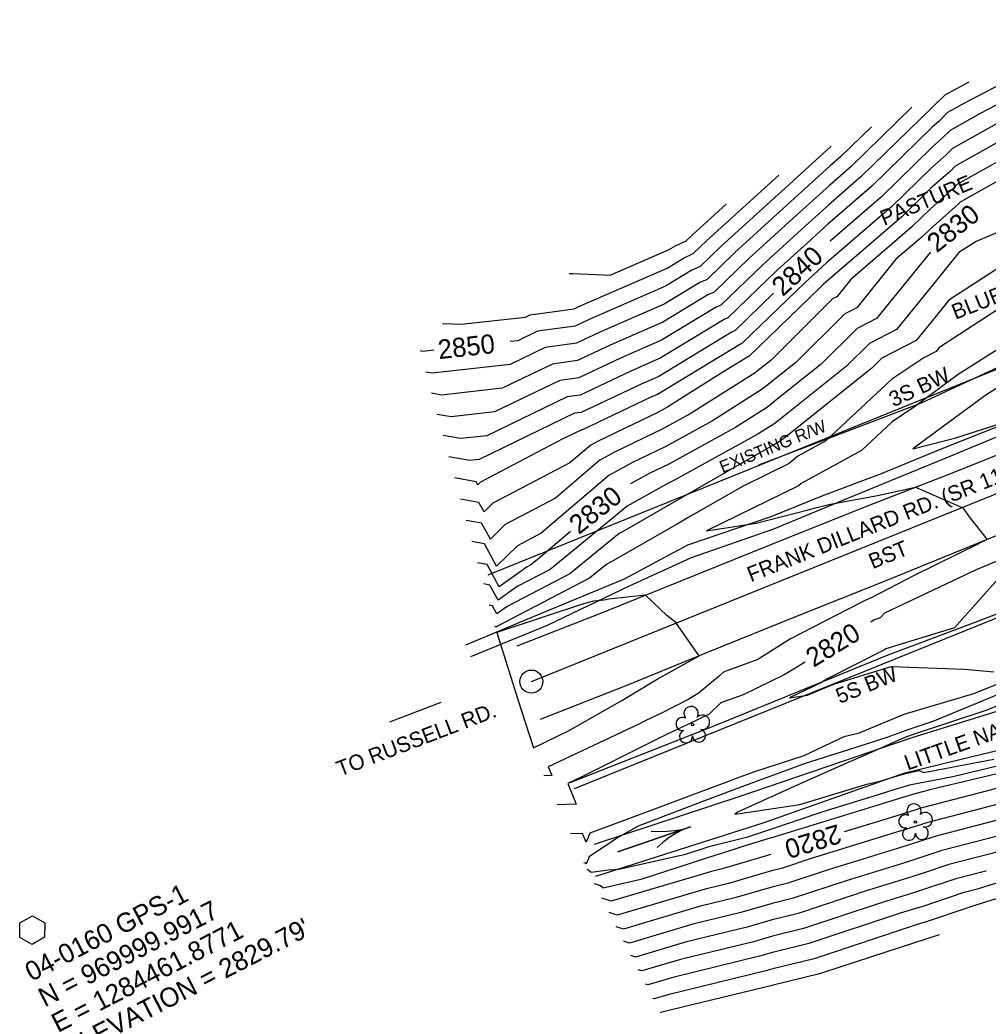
# Model space of a CAD drawing. Extents: x 1284446 to 1285480, y 969739 to 970628.
# Drawn here: x 1284458.6 to 1284710.8, y 969978.1 to 970236.9 of the extents above; entities that cross this region are included whole.
import ezdxf

# ---------------------------------------------------------------- set-up
doc = ezdxf.new("R2010")
doc.units = 0
for name, color, linetype in [('CTL Primary Horizontal and Vertical CELL', 7, 'Continuous'), ('CTL Primary Horizontal and Vertical Text', 7, 'Continuous'), ('Default', 7, 'Continuous'), ('Exist Horizontal Alignment', 7, 'Continuous'), ('Exist Horizontal Alignment Point', 7, 'Continuous'), ('Exist Hydro Jurisdictional Stream or Body of Water', 7, 'Continuous'), ('Exist Hydro Jurisdictional Stream or Body of Water Text', 7, 'Continuous'), ('Exist Hydro River Flow Arrow CELL', 7, 'Continuous'), ('Exist Other Culture Fence Line', 7, 'Continuous'), ('Exist Other Culture Fence Line Text', 7, 'Continuous'), ('Exist Right of Way Line', 7, 'Continuous'), ('Exist Right of Way Line Text', 7, 'Continuous'), ('Exist Roads EOP', 7, 'Continuous'), ('Exist Roads EOP Leader', 7, 'Continuous'), ('Exist Roads EOP Text', 7, 'Continuous'), ('Exist Utilities Power Joint Use Telephone Text', 7, 'Continuous'), ('Exist Utilities Telephone UG Cable SUE LOS D', 7, 'Continuous'), ('Exist Vegetation Tree CELL', 7, 'Continuous'), ('Exist Vegetation Woods Line Text', 7, 'Continuous')]:
    doc.layers.add(name, color=color, linetype=linetype)

msp = doc.modelspace()

# ---------------------------------------------------------------- linework, layer by layer
at = {"layer": 'CTL Primary Horizontal and Vertical CELL'}
msp.add_line((1284461.88, 969999.99), (1284461.88, 969999.99), dxfattribs=at)
msp.add_lwpolyline([(1284458.65, 970001.86), (1284461.9, 970003.68), (1284465.15, 970001.89), (1284465.1, 969998.16), (1284461.85, 969996.28), (1284458.65, 969998.09)], close=True, dxfattribs=at)
at = {"layer": 'Default'}
for points in [[(1284750.39, 970236.94), (1284749.29, 970236), (1284745.73, 970232.97), (1284744.91, 970232.37), (1284733.62, 970226.77), (1284728.14, 970222.74), (1284727.72, 970222.5), (1284708.72, 970212.53), (1284700.87, 970208.14), (1284698.91, 970206.2), (1284696.12, 970203.72), (1284683.01, 970190.92), (1284669.6, 970179.36)], [(1284739.84, 970233.74), (1284729.08, 970228.4), (1284727.62, 970227.33), (1284727.51, 970227.26), (1284704.48, 970215.18), (1284700.22, 970212.79), (1284697.9, 970210.5), (1284696.24, 970209.02), (1284680.37, 970193.53), (1284669.07, 970183.79), (1284663.63, 970178.84), (1284655.84, 970171.76), (1284643.02, 970159.37), (1284642.05, 970158.93), (1284625.37, 970148.84), (1284617.73, 970145.52), (1284604.5, 970139.27), (1284601.13, 970138.8), (1284580.23, 970128.69), (1284573.36, 970127.93), (1284568.84, 970128.73)], [(1284705.76, 970220.72), (1284700.24, 970217.82), (1284699.57, 970217.45), (1284696.89, 970214.81), (1284696.36, 970214.33), (1284677.73, 970196.14), (1284669.25, 970188.83), (1284662.22, 970182.44), (1284652.17, 970173.3), (1284641.21, 970162.72), (1284639.93, 970162.13), (1284625.73, 970153.54), (1284615.03, 970148.89), (1284604.19, 970143.76), (1284599.21, 970143.08), (1284582.24, 970134.87), (1284570.92, 970133.61), (1284567.34, 970134.25)], [(1284690.89, 970214.19), (1284675.09, 970198.76), (1284669.43, 970193.87), (1284660.82, 970186.05), (1284648.5, 970174.85), (1284639.41, 970166.06), (1284637.82, 970165.34), (1284626.09, 970158.24), (1284612.33, 970152.25), (1284603.88, 970148.26), (1284597.3, 970147.36), (1284584.26, 970141.05), (1284568.47, 970139.29), (1284565.84, 970139.76)], [(1284680.4, 970209.13), (1284672.45, 970201.37), (1284669.6, 970198.91), (1284659.41, 970189.65), (1284644.83, 970176.39), (1284637.6, 970169.4), (1284635.7, 970168.54), (1284626.45, 970162.94), (1284609.63, 970155.62), (1284603.56, 970152.76), (1284595.39, 970151.64), (1284586.27, 970147.23), (1284566.02, 970144.98), (1284564.34, 970145.28)], [(1284712.97, 970209.89), (1284701.53, 970203.48), (1284699.92, 970201.9), (1284696, 970198.41), (1284685.65, 970188.31), (1284668.72, 970173.71), (1284666.44, 970171.64), (1284663.18, 970168.68), (1284646.64, 970152.69), (1284646.28, 970152.52), (1284624.65, 970139.44), (1284623.14, 970138.79), (1284605.12, 970130.27), (1284604.96, 970130.25), (1284600, 970127.85), (1284578.6, 970116.64), (1284577.88, 970115.92), (1284577.45, 970116.7), (1284571.84, 970117.7)], [(1284717.21, 970207.24), (1284702.18, 970198.82), (1284700.93, 970197.59), (1284695.88, 970193.1), (1284688.29, 970185.69), (1284668.54, 970168.67), (1284667.85, 970168.04), (1284666.86, 970167.14), (1284648.45, 970149.34), (1284648.39, 970149.32), (1284642.34, 970145.66), (1284627.41, 970136.21), (1284624.95, 970134.85), (1284609.19, 970127.31), (1284607.28, 970126.25), (1284601.82, 970121.6), (1284581.81, 970111.11), (1284579.52, 970108.85), (1284578.16, 970111.33), (1284573.34, 970112.18)], [(1284721.46, 970204.6), (1284702.83, 970194.17), (1284701.94, 970193.29), (1284695.76, 970187.79), (1284690.93, 970183.08), (1284675.05, 970169.4), (1284671.37, 970164.87), (1284670.27, 970164.29), (1284654.16, 970148.31), (1284650.71, 970145.57), (1284650.1, 970145.08), (1284633.22, 970134.4), (1284625.91, 970130.37), (1284613.68, 970124.52), (1284609.66, 970122.29), (1284598.1, 970112.45), (1284585.02, 970105.59), (1284581.15, 970101.78), (1284578.88, 970105.95), (1284574.84, 970106.67)], [(1284669.9, 970204.07), (1284669.81, 970203.98), (1284669.78, 970203.95), (1284658.01, 970193.25), (1284641.15, 970177.93), (1284635.79, 970172.75), (1284633.59, 970171.75), (1284626.8, 970167.64), (1284606.92, 970158.99), (1284603.25, 970157.25), (1284593.47, 970155.91), (1284588.29, 970153.4), (1284586.34, 970153.19)], [(1284725.7, 970201.95), (1284703.48, 970189.51), (1284702.94, 970188.98), (1284695.64, 970182.48), (1284693.57, 970180.47), (1284686.78, 970174.62), (1284676.54, 970162.02), (1284673.48, 970160.44), (1284660.74, 970147.79), (1284653.07, 970141.7), (1284651.71, 970140.62), (1284639.03, 970132.59), (1284626.87, 970125.89), (1284618.18, 970121.74), (1284612.03, 970118.32), (1284594.38, 970103.3), (1284588.23, 970100.07), (1284582.79, 970094.71), (1284579.59, 970100.58), (1284576.34, 970101.15)], [(1284568.82, 970157.94), (1284569, 970157.93), (1284573.54, 970157.72), (1284590.3, 970159.58), (1284591.56, 970160.19), (1284602.94, 970161.75), (1284604.22, 970162.35), (1284627.16, 970172.34), (1284631.48, 970174.95), (1284633.98, 970176.09), (1284637.48, 970179.47), (1284656.27, 970196.55)], [(1284601.71, 970170.95), (1284602.73, 970170.9), (1284608.57, 970170.63), (1284612.39, 970170.45), (1284627.52, 970177.04), (1284629.36, 970178.16), (1284632.18, 970179.43), (1284633.81, 970181.01), (1284642.59, 970189)], [(1284727.79, 970187.79), (1284707.63, 970179.29), (1284703.18, 970176.39), (1284696.36, 970167.99), (1284686.89, 970156.34), (1284679.91, 970152.72), (1284673.91, 970146.76), (1284657.79, 970133.96), (1284654.94, 970131.69), (1284650.64, 970128.97), (1284628.78, 970116.93), (1284627.18, 970116.17), (1284616.78, 970110.39), (1284613.23, 970107.37), (1284596.77, 970093.9), (1284588.14, 970089.41), (1284583.18, 970085.86), (1284581.01, 970089.82), (1284579.33, 970090.12)], [(1284695.8, 970176.51), (1284695.71, 970176.39), (1284681.71, 970159.18), (1284676.7, 970156.58), (1284667.33, 970147.28), (1284655.43, 970137.83), (1284653.32, 970136.15), (1284644.84, 970130.78), (1284627.82, 970121.41), (1284622.68, 970118.95), (1284617.64, 970116.15)], [(1284714.06, 970172.78), (1284700.58, 970163.97), (1284697.01, 970159.58), (1284692.06, 970153.49), (1284683.13, 970148.86), (1284680.49, 970146.24), (1284660.15, 970130.09), (1284656.55, 970127.22), (1284656.45, 970127.16), (1284655.44, 970126.6), (1284630.92, 970112.52), (1284622.94, 970107.94), (1284615.56, 970103.71), (1284614.69, 970103.23), (1284601.88, 970092.75), (1284585.51, 970084.23), (1284582.87, 970082.34), (1284581.72, 970084.45), (1284580.83, 970084.61)], [(1284748.03, 970170.64), (1284743.49, 970166.53), (1284743.11, 970160.61), (1284730.72, 970152.47), (1284717.68, 970144.01), (1284710.17, 970139.24), (1284709.56, 970138.79), (1284691.19, 970125.24), (1284702.36, 970128.13), (1284714.55, 970132.09), (1284714.9, 970132.2), (1284715.19, 970132.29), (1284715.26, 970132.31)], [(1284654.92, 970165.78), (1284644.83, 970156.03), (1284644.16, 970155.73), (1284625.01, 970144.14), (1284620.44, 970142.15), (1284604.81, 970134.77), (1284603.04, 970134.53), (1284578.21, 970122.51), (1284575.81, 970122.24), (1284570.34, 970123.22)], [(1284720.49, 970166.27), (1284697.97, 970151.55), (1284697.66, 970151.17), (1284697.23, 970150.65), (1284694.07, 970149.01), (1284685.66, 970143.42), (1284668.55, 970127.4), (1284661.22, 970123.37), (1284658.97, 970121.46), (1284646.96, 970115.58), (1284634.03, 970108.16), (1284630.05, 970105.87), (1284613.42, 970096.34), (1284611.46, 970095.25), (1284607, 970091.6), (1284582.87, 970079.05), (1284582.57, 970078.83), (1284582.44, 970079.07), (1284582.33, 970079.09)], [(1284724.54, 970158.35), (1284703.64, 970145.09), (1284703.35, 970144.87), (1284691.64, 970136.24), (1284685.75, 970132.32), (1284677.8, 970124.88), (1284662.11, 970116.25), (1284661.41, 970115.66), (1284637.41, 970103.92), (1284650.4, 970105.95), (1284663.92, 970109.43), (1284665.84, 970109.91), (1284669.26, 970110.82), (1284681.92, 970113.1), (1284691.88, 970115.32), (1284703.36, 970110.26), (1284704.18, 970109.92), (1284706.11, 970107.2), (1284710.54, 970101.68), (1284708.52, 970100.7), (1284708.24, 970100.56), (1284691.48, 970092.28), (1284680.5, 970086.62), (1284678.5, 970085.7), (1284677.5, 970085.19), (1284677.37, 970085.11), (1284659.3, 970075.84), (1284650.8, 970070.44), (1284642.99, 970067.59), (1284641.83, 970067.18), (1284640.7, 970066.09), (1284635.28, 970061.56), (1284632.69, 970060.04), (1284625.76, 970056.44), (1284621.62, 970054.54), (1284619.65, 970053.55), (1284596.25, 970042.5), (1284597.15, 970040.23), (1284595.1, 970040.17)], [(1284566.46, 970150.98), (1284563.58, 970150.66), (1284562.84, 970150.79)], [(1284770.67, 970122.38), (1284755.04, 970114.8), (1284747.18, 970111.12), (1284744.66, 970109.99), (1284744.6, 970109.97), (1284719.18, 970098.66), (1284717.11, 970097.76), (1284716.01, 970097.26), (1284707.63, 970093.8), (1284683.78, 970082.51), (1284682.67, 970081.27), (1284681.13, 970080.8), (1284680.2, 970080.2)], [(1284602, 970103.79), (1284593.33, 970096.41), (1284591.66, 970095.05), (1284590.78, 970094.59), (1284583.48, 970089.37), (1284580.3, 970095.2), (1284577.83, 970095.64)], [(1284714.86, 970093.11), (1284708.34, 970085.8), (1284701.98, 970078.68), (1284684.11, 970073.22), (1284683.76, 970072.99), (1284669.03, 970065.5), (1284667.39, 970064.48), (1284659.08, 970060.44), (1284663.71, 970061.19), (1284668.67, 970063.23), (1284670.33, 970063.91), (1284685.5, 970068.61), (1284704.66, 970067.91), (1284712.27, 970067.27)], [(1284601.54, 970051.84), (1284615.42, 970059.75), (1284617.13, 970060.83), (1284619.13, 970062.01), (1284624.57, 970065.33), (1284635.49, 970071.4), (1284634.85, 970072.38), (1284629.43, 970080.04), (1284627.09, 970081.94), (1284621.51, 970087.19), (1284611.99, 970086.11), (1284610.76, 970085.89), (1284608.02, 970085.59), (1284605.37, 970084.91), (1284582.86, 970077.5), (1284588.28, 970060), (1284592.38, 970047.46), (1284601.54, 970051.84)], [(1284663.13, 970069.78), (1284657.68, 970066.41), (1284647.02, 970061.22), (1284641.17, 970059.2), (1284638.12, 970056.25), (1284632.74, 970053.58), (1284626.83, 970050.87), (1284605.48, 970040.14), (1284601.34, 970038.18), (1284603.47, 970032.75), (1284598.57, 970032.6)], [(1284713.63, 970064.24), (1284706.97, 970061.49), (1284688.81, 970056.16), (1284676.89, 970051.2), (1284673.19, 970050.31), (1284662.82, 970045.34), (1284649.69, 970041.13), (1284645.12, 970039.46), (1284643.18, 970038.72), (1284634.99, 970035.69), (1284624.58, 970031.72), (1284607.06, 970025.21), (1284606.06, 970022.89), (1284605.13, 970025.13), (1284602.05, 970025.04)], [(1284714.43, 970061.74), (1284696.35, 970054.27), (1284690.14, 970052.21), (1284684.43, 970050.17), (1284674.11, 970046.86), (1284663.11, 970043.33), (1284645.72, 970036.96), (1284638.33, 970034.15), (1284636.2, 970033.36), (1284619.6, 970027.03), (1284614.29, 970024.06), (1284606.86, 970019.05), (1284606.06, 970017.19), (1284605.94, 970017.49), (1284605.53, 970017.47)], [(1284814.4, 970041.99), (1284816.75, 970048.06), (1284820.23, 970054.6), (1284808.09, 970059.89), (1284797.6, 970049.66), (1284782.11, 970045.17), (1284777.42, 970043.78), (1284766.2, 970038.3), (1284764.73, 970037.66), (1284747.98, 970032.79), (1284736.56, 970027.66), (1284729.84, 970025.56), (1284728.99, 970025.34), (1284711.7, 970019.94), (1284700.56, 970017.04), (1284693.07, 970014.53), (1284689.78, 970013.52), (1284678.49, 970010.04), (1284661.34, 970004.35), (1284654.55, 970002.69), (1284648.03, 970000.78), (1284632.27, 969996.94), (1284618.99, 969993), (1284617.75, 969993.4)], [(1284715.23, 970059.24), (1284710.43, 970057.26), (1284690.77, 970050.73), (1284689.12, 970050.14), (1284677.5, 970045.04), (1284674.35, 970043.63), (1284662.01, 970038.18), (1284645.66, 970030.77), (1284645.39, 970030.62), (1284644.8, 970030.27), (1284645.37, 970030.31), (1284646.15, 970030.34), (1284661.77, 970032.68), (1284679.19, 970037.97), (1284682.61, 970038.74), (1284688.89, 970040.7), (1284692.83, 970041.59), (1284694.04, 970041.02), (1284712.27, 970044.53)], [(1284767.26, 970058.9), (1284755.85, 970053.33), (1284752.95, 970052.07), (1284748.38, 970050.74), (1284724.77, 970040.12), (1284723.76, 970039.81), (1284721.93, 970039.33), (1284719.26, 970038.5), (1284693.23, 970031.72), (1284691.68, 970031.2), (1284684.47, 970028.98), (1284673.31, 970025.55)], [(1284719.61, 970044.24), (1284701.55, 970039.94), (1284690.26, 970037.77), (1284686.24, 970036.55), (1284682.14, 970035.18), (1284667.71, 970030.81), (1284653.57, 970026.05), (1284647.83, 970024.1), (1284638.01, 970021.64), (1284632.01, 970019.68), (1284614.58, 970015.76), (1284611.96, 970015.61), (1284607.41, 970014.98), (1284606.56, 970015.69), (1284606.35, 970015.76)], [(1284720.42, 970042.39), (1284695.57, 970036.48), (1284691.4, 970035.39), (1284691.34, 970035.37), (1284683.15, 970032.85), (1284655, 970024.19), (1284654.49, 970024.02), (1284654.29, 970023.98), (1284646.88, 970021.8), (1284641.07, 970019.82), (1284639.88, 970019.53), (1284620.37, 970013.19), (1284610.49, 970010.96), (1284609.81, 970011.53), (1284608.25, 970012.03)], [(1284800.6, 970033.88), (1284803.46, 970041.27), (1284783.72, 970035.55), (1284777.1, 970033.58), (1284771.37, 970030.78), (1284770.62, 970030.45), (1284747.77, 970023.81), (1284742.46, 970021.42), (1284732.89, 970018.43), (1284732.52, 970018.34), (1284707.93, 970010.66), (1284704.22, 970009.69), (1284693.76, 970006.19), (1284692.44, 970005.78), (1284687.89, 970004.38), (1284664.08, 969996.48), (1284654.65, 969994.18), (1284651.28, 969993.19), (1284629.03, 969987.77), (1284622.19, 969985.75), (1284621.56, 969985.95)], [(1284717.37, 970033.86), (1284695.06, 970028.05), (1284692.03, 970027.03), (1284685.8, 970025.12), (1284664.39, 970018.53), (1284657.23, 970016.15), (1284654.4, 970015.46), (1284643.16, 970012.17), (1284637.12, 970010.7), (1284614.18, 970003.89), (1284612.05, 970004.58)], [(1284793.71, 970029.83), (1284795.26, 970033.85), (1284784.52, 970030.73), (1284776.95, 970028.48), (1284773.96, 970027.02), (1284773.57, 970026.85), (1284747.67, 970019.32), (1284745.4, 970018.31), (1284734.41, 970014.87), (1284734.28, 970014.84), (1284706.15, 970006.06), (1284705.98, 970006), (1284694.11, 970002.02), (1284693.76, 970001.92), (1284692.58, 970001.55), (1284665.45, 969992.54), (1284654.71, 969989.93), (1284652.9, 969989.4), (1284627.41, 969983.19), (1284623.79, 969982.12), (1284623.46, 969982.22)], [(1284715.48, 970029.22), (1284696.89, 970024.38), (1284692.38, 970022.86), (1284687.13, 970021.25), (1284669.09, 970015.7), (1284658.6, 970012.22), (1284654.45, 970011.21), (1284644.78, 970008.37), (1284635.5, 970006.11), (1284615.79, 970000.26), (1284613.95, 970000.85)], [(1284713.59, 970024.58), (1284698.72, 970020.71), (1284692.72, 970018.7), (1284688.46, 970017.38), (1284673.79, 970012.87), (1284659.97, 970008.28), (1284654.5, 970006.95), (1284646.41, 970004.58), (1284633.89, 970001.53), (1284617.39, 969996.63), (1284615.85, 969997.13)], [(1284654.2, 970019.68), (1284641.54, 970015.96), (1284638.74, 970015.28), (1284612.58, 970007.52), (1284610.15, 970008.31)], [(1284710.27, 970015.44), (1284709.82, 970015.3), (1284702.39, 970013.37), (1284693.41, 970010.36), (1284691.11, 970009.65), (1284683.19, 970007.21), (1284662.71, 970000.41), (1284654.6, 969998.44), (1284649.65, 969996.99), (1284630.65, 969992.36), (1284620.59, 969989.38), (1284619.66, 969989.68)], [(1284697.99, 969998.74), (1284684.11, 969994.25), (1284672.41, 969990.46), (1284666.82, 969988.61), (1284654.76, 969985.67), (1284654.52, 969985.6), (1284625.79, 969978.61), (1284625.39, 969978.49), (1284625.36, 969978.5)]]:
    msp.add_lwpolyline(points, dxfattribs=at)
at = {"layer": 'Exist Horizontal Alignment'}
msp.add_line((1284591.83, 970064.7), (1284846.18, 970167.48), dxfattribs=at)
at = {"layer": 'Exist Horizontal Alignment Point'}
msp.add_circle((1284591.83, 970064.7), 3, dxfattribs=at)
at = {"layer": 'Exist Hydro Jurisdictional Stream or Body of Water'}
for points in [[(1284608.58, 970014.06), (1284652.45, 970028.03), (1284689.07, 970040.96), (1284720.23, 970048.49), (1284751.74, 970066.17), (1284777.43, 970074.66), (1284799.45, 970086.45), (1284820.82, 970098.72), (1284840.81, 970117.42), (1284861.95, 970138.73), (1284875.04, 970148.73), (1284887.31, 970157.71)], [(1284608.31, 970022.37), (1284646.2, 970034.88), (1284690.96, 970050.11), (1284715.91, 970057.86), (1284748.8, 970074.52), (1284773.24, 970082.29), (1284795.23, 970094.54), (1284815.77, 970108.56), (1284836.54, 970123.66), (1284856.99, 970144.69), (1284864.89, 970151.94), (1284873.19, 970156.9)]]:
    msp.add_lwpolyline(points, dxfattribs=at)
at = {"layer": 'Exist Hydro River Flow Arrow CELL'}
msp.add_line((1284623.82, 970023.64), (1284623.82, 970023.64), dxfattribs=at)
msp.add_lwpolyline([(1284623.07, 970025.8), (1284625.11, 970025.68), (1284627.19, 970025.72), (1284629.27, 970025.94), (1284631.31, 970026.32), (1284633.27, 970026.92), (1284614.38, 970020.36), (1284633.27, 970026.92), (1284631.36, 970026.18), (1284629.52, 970025.21), (1284627.75, 970024.09), (1284626.1, 970022.84), (1284624.57, 970021.48)], dxfattribs=at)
at = {"layer": 'Exist Other Culture Fence Line'}
for points in [[(1284748.36, 970159.23), (1284717.21, 970148.3), (1284693.29, 970137.2), (1284650.97, 970121.07)], [(1284601.96, 970038.43), (1284640.3, 970053.54), (1284684.75, 970071.66), (1284706.29, 970079.75), (1284740.35, 970092.84), (1284765.34, 970102.18), (1284786.69, 970110.23), (1284807.57, 970118.44), (1284832.39, 970127.91), (1284856.77, 970145.02), (1284872.83, 970156.87)]]:
    msp.add_lwpolyline(points, dxfattribs=at)
at = {"layer": 'Exist Right of Way Line'}
for p, q in [((1284580.59, 970092.51), (1284834.94, 970195.29)), ((1284603.06, 970036.88), (1284857.42, 970139.66))]:
    msp.add_line(p, q, dxfattribs=at)
at = {"layer": 'Exist Roads EOP'}
for points in [[(1284588.17, 970073.97), (1284609.91, 970082.54), (1284630.17, 970090.65), (1284654.44, 970100.5), (1284678.03, 970109.93), (1284701.92, 970119.24), (1284725.51, 970128.63), (1284750.96, 970139.34), (1284775.61, 970149.46), (1284801.89, 970159.77), (1284826.13, 970169.58), (1284850.02, 970179.49), (1284870.96, 970188.88), (1284892.26, 970198.92), (1284892.63, 970199.46)], [(1284594.23, 970054.93), (1284616.52, 970063.71), (1284637.53, 970072.23), (1284661.54, 970081.97), (1284684.2, 970091.02), (1284708.29, 970100.77), (1284732.61, 970110.68), (1284757.85, 970120.85), (1284782.44, 970130.77), (1284809.22, 970141.4), (1284833.63, 970151.55), (1284857.38, 970161.54), (1284879.44, 970171.07), (1284883.53, 970171.7)]]:
    msp.add_lwpolyline(points, dxfattribs=at)
at = {"layer": 'Exist Roads EOP Leader'}
msp.add_lwpolyline([(1284555.02, 970054.18), (1284568.38, 970059.3)], dxfattribs=at)
at = {"layer": 'Exist Utilities Telephone UG Cable SUE LOS D'}
for points in [[(1284574.8, 970074.26), (1284594.5, 970082.54), (1284616.05, 970091.44), (1284632.57, 970100.26), (1284654.25, 970107.71), (1284668.02, 970113.22), (1284683.01, 970118.85), (1284698.34, 970125.18), (1284715.18, 970131.84), (1284729.87, 970137.49), (1284741.49, 970143.41), (1284741.82, 970148.26), (1284742.26, 970153.18)], [(1284576.08, 970071.21), (1284596.07, 970079.34), (1284617.42, 970089.61), (1284633.49, 970097.01), (1284654.93, 970104.42), (1284670.21, 970110.81), (1284685.4, 970117.07), (1284700.9, 970123.39), (1284712.2, 970128.05), (1284727.98, 970134.25), (1284736, 970137.68), (1284743.05, 970140.96), (1284744.07, 970146.74), (1284742.92, 970153.14)]]:
    msp.add_lwpolyline(points, dxfattribs=at)
at = {"layer": 'Exist Vegetation Tree CELL'}
for p, q in [((1284633.81, 970053.51), (1284633.81, 970053.51)), ((1284691.84, 970028.16), (1284691.84, 970028.16))]:
    msp.add_line(p, q, dxfattribs=at)
for centre in [(1284633.81, 970053.51), (1284691.84, 970028.16)]:
    msp.add_circle(centre, 0.326, dxfattribs=at)
for centre, radius, start, end in [((1284633.43, 970056.38), 1.86, 330.1651, 219.7134), ((1284631.21, 970053.66), 1.73, 62.6636, 279.3457), ((1284636.36, 970054.1), 1.9, 257.1011, 134.1999), ((1284632.11, 970050.39), 1.69, 111.5671, 6.231), ((1284635.48, 970050.61), 1.7, 181.2822, 74.56), ((1284691.46, 970031.03), 1.86, 330.1651, 219.7134), ((1284694.39, 970028.75), 1.9, 257.1011, 134.1999), ((1284689.24, 970028.31), 1.73, 62.6636, 279.3457), ((1284690.14, 970025.04), 1.69, 111.5671, 6.231), ((1284693.52, 970025.26), 1.7, 181.2822, 74.56)]:
    msp.add_arc(centre, radius, start, end, dxfattribs=at)

# ---------------------------------------------------------------- texts
at = {"layer": 'CTL Primary Horizontal and Vertical Text'}
for s, p in [('04-0160 GPS-1', (1284461.68, 969986.53)), ('N = 969999.9917', (1284465.12, 969979.87)), ('E = 1284461.8771', (1284468.56, 969973.21)), ("ELEVATION = 2829.79'", (1284472, 969966.54))]:
    msp.add_text(s, height=5, rotation=27.3235, dxfattribs=at).set_placement(p)
at = {"layer": 'Default'}
for s, rotation, p in [('2830', 38.5907, (1284697.4, 970176.14)), ('2840', 42.764, (1284657.3, 970164.73)), ('2850', 6.3341, (1284567.77, 970148.61)), ('2830', 38.3097, (1284604.2, 970102.81)), ('2820', 31.3818, (1284665.29, 970068.25)), ('2820', 197.0838, (1284671.58, 970027.63))]:
    msp.add_text(s, height=5, rotation=rotation, dxfattribs=at).set_placement(p)
at = {"layer": 'Exist Hydro Jurisdictional Stream or Body of Water Text'}
msp.add_text('LITTLE NAKED CRK.', height=4, rotation=19.5219, dxfattribs=at).set_placement((1284689.82, 970041.52))
at = {"layer": 'Exist Other Culture Fence Line Text'}
for s, rotation, p in [('3S BW', 24.8985, (1284686.12, 970136.08)), ('5S BW', 22.18, (1284672.14, 970058.87))]:
    msp.add_text(s, height=4, rotation=rotation, dxfattribs=at).set_placement(p)
at = {"layer": 'Exist Right of Way Line Text'}
msp.add_text('EXISTING R/W', height=3.2, rotation=22.0028, dxfattribs=at).set_placement((1284641.62, 970118.9))
at = {"layer": 'Exist Roads EOP Text'}
for s, rotation, p in [('FRANK DILLARD RD. (SR 1115)', 21.6942, (1284648.99, 970090.54)), ('BST', 22.1175, (1284680.68, 970093.94)), ('TO RUSSELL RD.', 20.9239, (1284542.02, 970039.93))]:
    msp.add_text(s, height=4, rotation=rotation, dxfattribs=at).set_placement(p)
at = {"layer": 'Exist Utilities Power Joint Use Telephone Text'}
msp.add_text('BLUE RIDGE ELECTRIC', height=4, rotation=21.458, dxfattribs=at).set_placement((1284702.27, 970158.87))
at = {"layer": 'Exist Vegetation Woods Line Text'}
msp.add_text('PASTURE', height=4, rotation=22.67, dxfattribs=at).set_placement((1284683.69, 970183.28))

doc.saveas('drawing.dxf')
